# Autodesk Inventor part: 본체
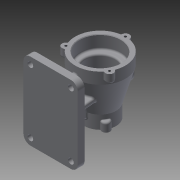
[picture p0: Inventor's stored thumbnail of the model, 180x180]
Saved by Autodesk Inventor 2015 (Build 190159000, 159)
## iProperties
Created: 2020-03
Part Number: 본체
Material: 일반
Document SubType Name: Modeling
Designer: Administrator
Density: 1 g/cm^3
Appearance: 기본값
Author: Administrator
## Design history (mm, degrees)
sketch "스케치1"
  geometry: L1 (47.5, -67.5)-(-47.5, -67.5); L2 (-47.5, -67.5)-(-47.5, 67.5); L3 (-47.5, 67.5)-(47.5, 67.5); L4 (47.5, 67.5)-(47.5, -67.5); L5 (47.5, -67.5)-(-47.5, 67.5); L6 (-47.5, -67.5)-(47.5, 67.5); 1 further point
  constraints: 12 end point, 2 midpoint, 2 parallel, 1 horizontal, 1 perpendicular
  dimensions: "d0" = 95 distance of L2.end L3.end; "d1" = 135 distance of L1.end L2.end
extrude "돌출1" new body sketch "스케치1" distance "d2" = 12; taper "d3" = 0 deg
fillet "모깎기1" dims "d4" = 12
sketch "스케치2"
  geometry: L1 (-47.5, 55.5)-(-47.5, -55.5) reference; L2 (-35.5, -67.5)-(35.5, -67.5) reference; L3 (47.5, -55.5)-(47.5, 55.5) reference; L4 (35.5, 67.5)-(-35.5, 67.5) reference; A1 r 12 centre (-35.5, 55.5) between (-35.5, 67.5) and (-47.5, 55.5) reference; A2 r 12 centre (-35.5, -55.5) between (-47.5, -55.5) and (-35.5, -67.5) reference; A3 r 12 centre (35.5, -55.5) between (35.5, -67.5) and (47.5, -55.5) reference; A4 r 12 centre (35.5, 55.5) between (47.5, 55.5) and (35.5, 67.5) reference; 5 further points
  constraints: 4 coincident
hole "구멍1" sketch "스케치2" at (-35.5, -55.5), (35.5, -55.5), (-35.5, 55.5), (35.5, 55.5) diameter "d5" = 10; stored, may be unused: countersink angle "d9" = 90 deg, drill point angle "d11" = 118 deg; dims "d6" = 6, "d7" = 4, "d8" = 2, "d10" = 8
sketch "스케치3"
  geometry: L1 (0, 0)-(0, 12); L2 (0, 12)-(25, 12); L3 (25, 12)-(18.439, 86.997); L4 (18.439, 86.997)-(-18.439, 86.997) reference; L5 (0, 12)-(-25, 12); L6 (-25, 12)-(-18.439, 86.997)
  constraints: 12 end point, 2 horizontal, 1 parallel, 1 perpendicular, 1 vertical
  dimensions: "d12" = 12 distance of L1.start L1.end; "d13" = 25 distance of L1.end L2.end; "d14" = 85 deg angle of L3 L2; "d15" = 25 distance of L1.end L5.end; "d16" = 85 deg angle of L5 L6
extrude "돌출2" join sketch "스케치3" stored distance "d17" = 8; taper "d18" = 0 deg
sketch "스케치4"
  geometry: L1 (-4, -37)-(4, -37); L2 (4, -37)-(4, 37); L3 (4, 37)-(-4, 37); L4 (-4, 37)-(-4, -37); L5 (-4, -37)-(4, 37); L6 (4, -37)-(-4, 37); 1 further point
  constraints: 12 end point, 2 midpoint, 2 parallel, 1 horizontal, 1 perpendicular
  dimensions: "d19" = 8 distance of L3.end L2.end; "d20" = 74 distance of L2.end L1.end
extrude "돌출3" join sketch "스케치4" distance "d21" = 78; taper "d22" = 0 deg
sketch "스케치5"
  geometry: L1 (0, 0)-(87, 0); L2 (86.997, 50)-(86.997, -50); L3 (86.997, -4)-(86.997, 4) reference; L4 (86.997, 50)-(130.997, 50); L5 (130.997, 50)-(130.997, 30); L6 (59.497, -50)-(114.497, -50); L7 (130.997, 30)-(114.497, -27); L8 (114.497, -50)-(114.497, -27); 1 further point
  constraints: 14 end point, 3 horizontal, 3 midpoint, 2 vertical, 1 perpendicular
  dimensions: "d23" = 87 distance of L1.start L1.end; "d24" = 100 distance of L2.end L2.start; "d25" = 44 distance of L2.start L4.end; "d26" = 20 distance of L4.end L5.end; "d68" = 55 distance of L6.start L6.end
revolve "회전1" sketch "스케치5" stored, may be unused: angle "d30" = 90 deg
sketch "스케치6"
  geometry: C1 r 7 at (0, 44); 2 further points
  constraints: 1 centre point, 1 vertical alignment, 1 other
  dimensions: "d31" = 7 radius of C1
extrude "돌출4" join sketch "스케치6" distance "d32" = 15; taper "d33" = 0 deg
sketch "스케치8"
  geometry: A1 r 44 centre (0, -44) between (-34.134, -71.765) and (34.134, -71.765) reference; A2 r 7 centre (38.105, -66) between (34.134, -71.765) and (41.112, -59.679) reference; A3 r 44 centre (0, -44) between (41.112, -59.679) and (6.978, -0.557) reference; A4 r 7 centre (0, 0) between (6.978, -0.557) and (-6.978, -0.557) reference; A5 r 44 centre (0, -44) between (-6.978, -0.557) and (-41.112, -59.679) reference; A6 r 7 centre (-38.105, -66) between (-41.112, -59.679) and (-34.134, -71.765) reference; 4 further points
  constraints: 3 coincident
hole "구멍2" sketch "스케치8" at (0, 0), (-38.105, -66), (38.105, -66) diameter "d43" = 4.134; stored, may be unused: countersink angle "d47" = 90 deg, drill point angle "d49" = 118 deg; dims "d44" = 9, "d45" = 4, "d46" = 2, "d48" = 11
fillet "모깎기2" dims "d57" = 3
fillet "모깎기3" dims "d58" = 1
node "작업 평면1"
sketch "스케치10"
  geometry: C1 r 15 at (0, 0); 1 further point
  constraints: 1 centre point, 1 coincident
  dimensions: "d60" = 30 diameter of C1
extrude "돌출6" join sketch "스케치10" stored distance "d61" = 15; taper "d62" = 0 deg
sketch "스케치11"
  geometry: C1 r 2.067 at (-38.105, -66) reference; C2 r 2.067 at (0, 0) reference; C3 r 2.067 at (38.105, -66) reference; C4 r 36 at (0, -44); A1 r 1 centre (34.354, -73.066) between (34.823, -72.183) and (33.59, -72.42) reference; A2 r 7 centre (38.105, -66) between (34.823, -72.183) and (41.818, -60.066) reference; A3 r 1 centre (42.349, -59.218) between (41.408, -58.88) and (41.818, -60.066) reference; A4 r 44 centre (0, -44) between (41.408, -58.88) and (7.817, -0.7) reference; A5 r 1 centre (7.995, 0.284) between (6.996, 0.249) and (7.817, -0.7) reference; A6 r 7 centre (0, 0) between (6.996, 0.249) and (-6.996, 0.249) reference; A7 r 1 centre (-7.995, 0.284) between (-7.817, -0.7) and (-6.996, 0.249) reference; A8 r 44 centre (0, -44) between (-7.817, -0.7) and (-41.408, -58.88) reference; A9 r 1 centre (-42.349, -59.218) between (-41.818, -60.066) and (-41.408, -58.88) reference; A10 r 7 centre (-38.105, -66) between (-41.818, -60.066) and (-34.823, -72.183) reference; A11 r 1 centre (-34.354, -73.066) between (-33.59, -72.42) and (-34.823, -72.183) reference; A12 r 44 centre (0, -44) between (-33.59, -72.42) and (33.59, -72.42) reference; 1 further point
  constraints: 1 centre point, 1 coincident
  dimensions: "d64" = 72 diameter of C4
extrude "돌출7" cut sketch "스케치11" distance "d65" = 23; taper "d66" = 0 deg
sketch "스케치12"
  geometry: C1 r 36 at (0, 0) reference; C2 r 26 at (0, 0); 1 further point
  constraints: 1 centre point, 1 coincident
  dimensions: "d67" = 52 diameter of C2
extrude "돌출8" cut sketch "스케치12" distance "d70" = 47; taper "d71" = 0 deg
sketch "스케치13"
  geometry: C1 r 7 at (0, 27.5); 2 further points
  constraints: 1 centre point, 1 vertical alignment, 1 other
  dimensions: "d72" = 14 diameter of C1
extrude "돌출9" join sketch "스케치13" distance "d73" = 15; taper "d74" = 0 deg
sketch "스케치14"
  geometry: A1 r 27.5 centre (0, -27.5) between (26.516, -34.792) and (6.943, -0.891) reference; A2 r 7 centre (0, 0) between (6.943, -0.891) and (-6.943, -0.891) reference; A3 r 27.5 centre (0, -27.5) between (-6.943, -0.891) and (-26.516, -34.792) reference; A4 r 7 centre (-23.816, -41.25) between (-26.516, -34.792) and (-19.573, -46.817) reference; A5 r 27.5 centre (0, -27.5) between (-19.573, -46.817) and (19.573, -46.817) reference; A6 r 7 centre (23.816, -41.25) between (19.573, -46.817) and (26.516, -34.792) reference; 4 further points
  constraints: 3 coincident
hole "구멍4" sketch "스케치14" at (0, 0), (-23.816, -41.25), (23.816, -41.25) diameter "d78" = 4.134; stored, may be unused: countersink angle "d82" = 90 deg, drill point angle "d84" = 118 deg; dims "d79" = 9, "d80" = 4, "d81" = 2, "d83" = 11
fillet "모깎기5" dims "d85" = 3
fillet "모깎기6" dims "d86" = 1
sketch "스케치15"
  geometry: C1 r 26 at (0, 0) reference; C2 r 20 at (0, 0); 1 further point
  constraints: 1 centre point, 1 coincident
  dimensions: "d87" = 40 diameter of C2
extrude "돌출10" cut sketch "스케치15" distance "d88" = 30; taper "d89" = 0 deg
sketch "스케치16"
  geometry: C1 r 15 at (0, 0) reference; C2 r 10 at (0, 0); 1 further point
  constraints: 1 centre point, 1 coincident
  dimensions: "d90" = 20 diameter of C2
extrude "돌출11" cut sketch "스케치16" distance "d91" = 30; taper "d92" = 0 deg
fillet "모깎기7" dims "d93" = 3
chamfer "모따기1" distance "d94" = 1; stored, may be unused: second distance "d95" = 2, angle "d96" = 45 deg
fillet "모깎기8" dims "d97" = 3
fillet "모깎기9" dims "d98" = 3
fillet "모깎기10" dims "d99" = 3
fillet "모깎기11" dims "d100" = 3
fillet "모깎기12" dims "d101" = 1
node "솔리드1"
pattern_circular "원형 패턴1" dims angle "d35" = 360 deg
pattern_circular "원형 패턴3" dims angle "d76" = 360 deg
node "투영된 루프1"
node "투영된 루프2"
node "투영된 루프4"
node "투영된 루프6"
node "투영된 루프7"
node "투영된 루프8"
node "투영된 루프9"
node "투영된 루프10"
node "투영된 루프11"
other parameters: "d59" = 132
